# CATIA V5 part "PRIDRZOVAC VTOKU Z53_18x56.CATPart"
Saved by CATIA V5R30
Part number: PRIDRZOVAC VTOKU Z53/18x56
Bounding box of the stored display mesh (mm): x 0 to 56, y -10.99 to 10.99, z -11 to 11
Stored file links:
  C:\Users\ondra\Desktop\PŘÍLOHA P III\CATIA\PRIDRZOVAC VTOKU Z53_18x56.CATPart
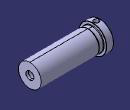
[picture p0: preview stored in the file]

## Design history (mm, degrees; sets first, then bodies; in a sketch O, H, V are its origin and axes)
Set1
  DatumSurface1 to DatumSurface33 "Z53/18x5"
  Plane1: type Offset, RefPlane xy-plane, Offset 6
  Join1: Elements (DatumSurface1; DatumSurface2; DatumSurface3; DatumSurface4; DatumSurface5; DatumSurface6; DatumSurface7; DatumSurface8; DatumSurface9; DatumSurface10; DatumSurface11; DatumSurface12; DatumSurface13; DatumSurface14; DatumSurface15; DatumSurface16; DatumSurface17; DatumSurface18; DatumSurface19; DatumSurface20; DatumSurface21; DatumSurface22; DatumSurface23; DatumSurface24; DatumSurface25; DatumSurface26; DatumSurface27; DatumSurface28; DatumSurface29; DatumSurface30; DatumSurface31; DatumSurface32; DatumSurface33)
Body1 (main body)
  CloseSurface1: CloseElement Join1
